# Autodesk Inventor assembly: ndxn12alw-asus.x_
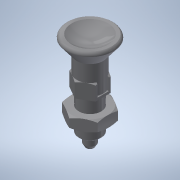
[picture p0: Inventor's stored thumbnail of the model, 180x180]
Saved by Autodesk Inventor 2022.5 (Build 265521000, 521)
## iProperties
Part Number: ndxn12alw-asus.x_
Material: 一般
Document SubType Name: Assembly
Designer: ImaoCorp
Sending System: SOLIDWORKS 2017-2017317
MC: AMD64
MC_MODEL: Intel64 Family 6 Model 60 Stepping 3, GenuineIntel
OS: Windows_NT
FRU: Parasolid Version 29.0, build 201,  4-17-2017
FORMAT: text
GUISE: transmit
KEY: ndxn12alw-asus
FILE: ndxn12alw-asus.x_t
DATE: Wed Sep 04 15:29:07 2019
Author: ImaoCorp
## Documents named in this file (3)
- X:\14_SW2022-Inv2022\00_全2023-1023新製品(TCC)まで\n\ndxn12alw-asus\NDXN12ALW-ASUS.iam
- X:\14_SW2022-Inv2022\00_全2023-1023新製品(TCC)まで\n\ndxn12alw-asus\ndxn12alw-asus_01.ipt
- X:\14_SW2022-Inv2022\00_全2023-1023新製品(TCC)まで\n\ndxn12alw-asus\ndxn12alw-asus_02.ipt
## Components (2 placed, 2 different names)
1. ndxn12alw-asus_01
2. ndxn12alw-asus_02
